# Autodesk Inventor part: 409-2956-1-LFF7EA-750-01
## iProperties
Created: 2010-06
Part Number: 409-2956-1-LFF7EA-750-01
Material: Sch40 CS PIPE SEAMLESS
Description: PIPE
Document SubType Name: Modeling
Designer: S. Boerckel
Engineer: Steve Boerckel
Mass: 2488.07 g
Surface Area: 1634.44 cm^2
Volume: 316.951 cm^3
Density: 7.85 g/cm^3
Cost Center: 4"
SMR: =<COST CENTER> - <Material>
Length: 18.000 in
Title: 2"
Author: S. Boerckel
Revision Number: B
Subject: DEMIN WATER FORWARDING PUMP SKID-7EA
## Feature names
1. Extrusion1
